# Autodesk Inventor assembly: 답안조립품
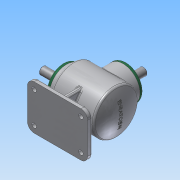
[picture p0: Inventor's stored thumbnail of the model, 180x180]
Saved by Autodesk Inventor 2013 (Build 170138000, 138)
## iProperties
Created: 2016-09
Part Number: 답안조립품
Document SubType Name: Assembly
Designer: Administrator
Author: Administrator
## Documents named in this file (14)
- C:\Users\Administrator\Desktop\460908V1012\답안조립품.iam
- C:\Users\Administrator\Desktop\460908V1012\M4.ipt
- C:\Users\Administrator\Desktop\460908V1012\메인 베벨기어.ipt
- C:\Users\Administrator\Desktop\460908V1012\메인 축.ipt
- 메인 축.ipt
- C:\Users\Administrator\Desktop\460908V1012\베어링 6203.ipt
- C:\Users\Administrator\Desktop\460908V1012\본체.ipt
- C:\Users\Administrator\Desktop\460908V1012\서브 베벨기어.ipt
- C:\Users\Administrator\Desktop\460908V1012\서브 축.ipt
- 서브 축.ipt
- C:\Users\Administrator\Desktop\460908V1012\오일실 17 32 8.ipt
- C:\Users\Administrator\Desktop\460908V1012\커버.ipt
- C:\Users\Administrator\Desktop\460908V1012\키 4x4.ipt
- C:\Users\Administrator\Desktop\460908V1012\키 5x5.ipt
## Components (8 placed, 1 different names)
1. M4:2
2. M4:3
3. M4:4
4. M4:5
5. M4:1
6. M4:6
7. M4:7
8. M4:8
